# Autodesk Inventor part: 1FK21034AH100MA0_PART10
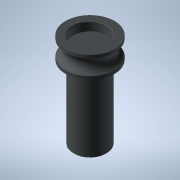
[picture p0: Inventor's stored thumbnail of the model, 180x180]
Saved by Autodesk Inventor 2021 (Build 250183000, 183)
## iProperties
Created: 2025-04
Part Number: 1FK21034AH100MA0_PART10
Material: Generic
Catalog Web Link: www.3dfindit.com
Description: -Servo synchronous motor
Document SubType Name: Modeling
Designer: psAdmin
Mass: 6.43867 g
Surface Area: 29.6592 cm^2
Volume: 6.43867 cm^3
Density: 1 g/cm^3
Appearance: PSOLRGB-212-217-219
Category: PARTsolutions
Title: 1FK21034AH100MA0_PART10
Author: Cadenas PARTsolutions
Comments: Servo synchronous motor
Sending System: PARTsolutions
Preprocessor: ST-DEVELOPER v19.3
PSOL_IDENT_0: {$CADENAS_DATA/23d-libs/siemens_ag/_cat_/39/97/1fk21034ah100ma0.prj},216 {VTYP=3D},{NB=1FK21034AH100
PSOL_IDENT_1: MA0_PART10},{LINA=1FK21034AH100MA0_PART10},{NN=1FK21034AH100MA0_PART10},{NOPRJ=TRUE},{DATE=19.08.202
PSOL_IDENT_2: 5 14:00:33},{GEOMDATE=30.07.2025 02:02:21},{VERSION=},{LINEID=10},{WBVAR=},{WBNUMERIC=}  {NB=1FK2103
PSOL_IDENT_3: 4AH100MA0_PART10},{LINA=1FK21034AH100MA0_PART10},{KT=DUMMY},{PREVIEW=../../../_pool_/d3/78/p_d211_xx
PSOL_IDENT_4: _00934j.png},{DESCSHORT=SIMOTICS S-1FK2 HD, SINAMICS S210 3AC 400V-480V, 1.01 Nm, 4500 rpm},{DESCLON
PSOL_IDENT_5: G=SIMOTICS S-1FK2 HD servo motor M0=1.27 Nm; PN = 0.48 kW at nN=4500 rpm (380-480 V); PN = 0.3 kW at
PSOL_IDENT_6: nN=2500 rpm (200-240 V); with holding brake; degree of protection IP64; cylindrical shaft D14 x 30
PSOL_IDENT_7: mm; absolute encoder 22-bit + 12-bit multiturn (encoder AM22DQC); with OCC interface; plug size M17,
PSOL_IDENT_8: rotatable; SIMOTICS S-1FK2 servomotorfor a wide range of uses in industrial environments. SIMOTICS
PSOL_IDENT_9: S‑1FK2 servomotors are compact synchronous motors with a high dynamic performance that set themselve
PSOL_IDENT_10: s apart as a result of their high power density, degree of protection and overload capability. The m
PSOL_IDENT_11: otors are available in two variants: as High Dynamic variant (highest dynamic performance as a resul
PSOL_IDENT_12: t of the low intrinsic moment of inertia for applications demanding a high dynamic performance with
PSOL_IDENT_13: low moved masses) - and as Compact variant (precise and stable closed-loop control for medium up to
PSOL_IDENT_14: large moved masses as a result of a medium intrinsic moment of inertia). SIMOTICSS‑1FK2 servomotors
PSOL_IDENT_15: fully exploit their strengths in a system with the SINAMICSS210 frequency converter and simple conne
PSOL_IDENT_16: ction using the one cable connection (OCC). Advantages include the short control and positioning tim
PSOL_IDENT_17: es, fast and precise correction of disturbing quantities as well as stable control with a high dynam
PSOL_IDENT_18: ic performance. The servo motors can be configured to address a wide range of requirements. For exam
PSOL_IDENT_19: ple with and without holding brake, IP64 or IP65 degree of protection, singleturn or multiturn absol
PSOL_IDENT_20: ute encoders - to name just a few. Further, the servomotors are available in different shaft heights
PSOL_IDENT_21: extending from 20 to 100. A shaft sealing ring is available to achieve an IP65 degree of protection
PSOL_IDENT_22: and for subsequent mounting at the motor or as spare part. SIMOTICS - the optimum motor for each an
PSOL_IDENT_23: d every motion control application.},{INTNO=195125454019},{SUPPLIERALTNO=1FK2103-4AH10-0MA0},{MANUID=
PSOL_IDENT_24: 1FK21034AH100MA0},{MANUNAME=Siemens},{MANUTYPEDESC=SYNCHRONOUS MOTOR 1FK2 HD 1,27 NM},{AAU732=SIMOTI
PSOL_IDENT_25: CS},{AAO057=S-1FK2},{AAU734=SIMOTICS S-1FK2 HD servo motor M0=1.27 Nm; PN = 0.48 kW at nN=4500 rpm (
PSOL_IDENT_26: 380-480 V); PN = 0.3 kW at nN=2500 rpm (200-240 V); with holding brake; degree of protection IP64; c
PSOL_IDENT_27: ylindrical shaft D14 x 30 mm; absolute encoder 22-bit + 12-bit multiturn (encoder AM22DQC); with OCC
PSOL_IDENT_28: interface; plug size M17, rotatable;},{AAW338=SYNCHRONOUS MOTOR 1FK2 HD 1,27 NM},{AAO742=SIMOTICS},
PSOL_IDENT_29: {AAO663=4034106444921},{NOCUPEROU=1},{PRICEQUANTITY=1},{QUANTITYMIN=1},{QUANTITYINT=1},{CTN=85015100
PSOL_IDENT_30: },{COO=RO},{AAO676=1FK2103-4AH10-0MA0},{AAO677=Siemens AG},{ORDERUNIT=C62},{CONTENTUNIT=C62}
NB: 1FK21034AH100MA0_PART10
NT: Servo synchronous motor
NBSYN: $MANUID._PART10
LINA: 1FK21034AH100MA0_PART10
CATALOG: SIEMENS
PREVIEW: ../../../_pool_/d3/78/p_d211_xx_00934j.png
DESCSHORT: SIMOTICS S-1FK2 HD, SINAMICS S210 3AC 400V-480V, 1.01 Nm, 4500 rpm
DESCLONG: SIMOTICS S-1FK2 HD servo motor M0=1.27 Nm; PN = 0.48 kW at nN=4500 rpm (380-480 V); PN = 0.3 kW at nN=2500 rpm (200-240 V); with holding brake; degree of protec
INTNO: 195125454019
SUPPLIERALTNO: 1FK2103-4AH10-0MA0
MANUID: 1FK21034AH100MA0
MANUNAME: Siemens
MANUTYPEDESC: SYNCHRONOUS MOTOR 1FK2 HD 1,27 NM
AAU732: SIMOTICS
AAO057: S-1FK2
AAU734: SIMOTICS S-1FK2 HD servo motor M0=1.27 Nm; PN = 0.48 kW at nN=4500 rpm (380-480 V); PN = 0.3 kW at nN=2500 rpm (200-240 V); with holding brake; degree of protec
AAW338: SYNCHRONOUS MOTOR 1FK2 HD 1,27 NM
AAO742: SIMOTICS
AAO663: 4034106444921.0
NOCUPEROU: 1
PRICEQUANTITY: 1
QUANTITYMIN: 1
QUANTITYINT: 1
CTN: 85015100
COO: RO
ARTICLENO: 1FK21034AH100MA0_PART10
BOMINFO: 1FK21034AH100MA0_PART10
CREATOR: CADENAS GmbH
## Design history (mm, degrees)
feature "2025_04_17_15_09_00_0361"
body "Solid1"
